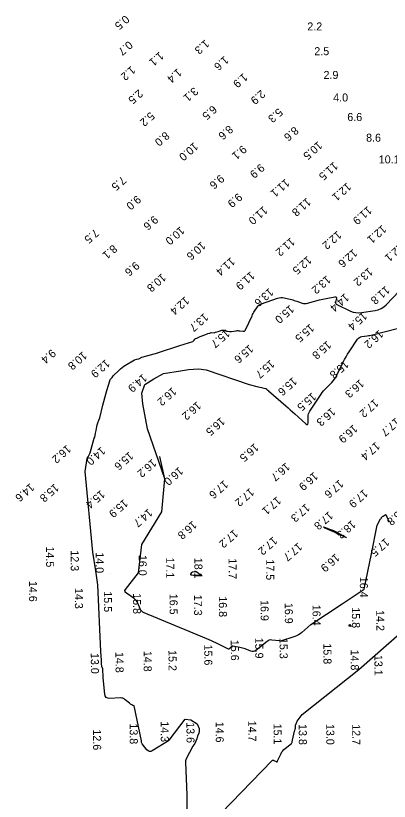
# Model space of a CAD drawing. Extents: x 824616 to 827440, y 158441 to 163197.
# Drawn here: x 824616.2 to 824849.5, y 161147.6 to 161638.3 of the extents above; entities that cross this region are included whole.
import ezdxf

# ---------------------------------------------------------------- set-up
doc = ezdxf.new("R2010")
doc.units = 0
for name, color, linetype in [('V-CHAN-CONT-EL14', 7, 'Continuous'), ('V-CHAN-CONT-EL16', 7, 'Continuous'), ('V-CHAN-CONT-EL18', 7, 'Continuous'), ('V-TOPO-SOUN', 7, 'Continuous')]:
    doc.layers.add(name, color=color, linetype=linetype)

msp = doc.modelspace()

# ---------------------------------------------------------------- linework, layer by layer
at = {"layer": 'V-CHAN-CONT-EL14'}
for points in [[(824704.71, 161427.68), (824718.66, 161432.2), (824726.88, 161434.8), (824727.67, 161435.56), (824728.08, 161436.17), (824728.41, 161436.69), (824729.26, 161436.92), (824731.44, 161438.01), (824734.23, 161438.98), (824736.28, 161439.79), (824737.33, 161440.05), (824738.35, 161440.37), (824740.07, 161440.24), (824740.9, 161440.6), (824741.73, 161440.84), (824742.6, 161440.96), (824743.91, 161441.51), (824744.34, 161441.65), (824744.89, 161441.79), (824745.19, 161441.82), (824745.47, 161441.86), (824745.61, 161441.91), (824745.73, 161441.93), (824745.83, 161441.95), (824745.99, 161441.92), (824746.13, 161441.88), (824746.26, 161441.85), (824746.57, 161441.76), (824746.78, 161441.75), (824746.96, 161441.72), (824747.15, 161441.65), (824747.38, 161441.52), (824747.65, 161441.38), (824747.92, 161441.28), (824748.2, 161441.2), (824748.5, 161441.16), (824749.74, 161441.04), (824750.05, 161441.02), (824750.36, 161441.02), (824750.67, 161441.03), (824750.97, 161441.07), (824753.95, 161441.51), (824754.48, 161441.57), (824755.01, 161441.59), (824755.55, 161441.56), (824756.08, 161441.5), (824758.21, 161441.19), (824758.7, 161441.18), (824759.12, 161441.31), (824759.46, 161441.59), (824759.72, 161442.01), (824763.78, 161450.91), (824764.13, 161451.64), (824764.51, 161452.36), (824764.93, 161453.06), (824765.37, 161453.75), (824767.21, 161456.45), (824767.7, 161457.08), (824768.28, 161457.6), (824768.93, 161458.02), (824769.67, 161458.34), (824779.68, 161461.81), (824780.7, 161462.08), (824781.74, 161462.21), (824782.77, 161462.19), (824783.82, 161462.02), (824788.41, 161460.94), (824789.26, 161460.73), (824790.11, 161460.49), (824790.95, 161460.24), (824791.78, 161459.97), (824795.1, 161458.84), (824795.94, 161458.62), (824796.77, 161458.53), (824797.61, 161458.57), (824798.46, 161458.73), (824805.83, 161460.74), (824806.91, 161461.02), (824807.99, 161461.28), (824809.07, 161461.51), (824810.16, 161461.73), (824815.54, 161462.74), (824816.04, 161462.76), (824816.36, 161462.61), (824816.49, 161462.29), (824816.46, 161461.8), (824815.94, 161459.47), (824815.89, 161458.93), (824816.02, 161458.47), (824816.3, 161458.1), (824816.76, 161457.81), (824825.32, 161453.83), (824826.95, 161453.21), (824828.61, 161452.84), (824830.31, 161452.72), (824832.04, 161452.85), (824840.69, 161454.11), (824842.64, 161454.56), (824844.43, 161455.31), (824846.07, 161456.35), (824847.55, 161457.69), (824855.79, 161466.49)], [(824670.68, 161395.08), (824673.17, 161404.29), (824674.26, 161408.11), (824675.29, 161411), (824676.35, 161412.37), (824677.01, 161413.25), (824680.72, 161416.91), (824681.67, 161417.8), (824682.67, 161418.61), (824683.73, 161419.36), (824684.83, 161420.05), (824690.46, 161423.29), (824691.77, 161423.86), (824693.09, 161424.04), (824694.87, 161425.06), (824698.02, 161425.89), (824704.88, 161427.73)], [(824666.16, 161291.46), (824664.39, 161303.13), (824659.58, 161353.61), (824660.85, 161361.63), (824661.45, 161362.75), (824662.63, 161365.23), (824665.14, 161374.39), (824665.56, 161375.13), (824665.84, 161376.02), (824666.13, 161377.55), (824666.45, 161379.27), (824666.83, 161381.62), (824667.04, 161382.68), (824667.44, 161383.96), (824668.03, 161385.73), (824668.76, 161387.13), (824670.68, 161395.08)], [(824669.31, 161241.2), (824667.57, 161282.73), (824666.16, 161291.46)], [(824675.23, 161289.84), (824675.15, 161289.85)], [(824830.5, 161229.86), (824857.8, 161253.75)], [(824694.69, 161185.29), (824690.25, 161207.15), (824689.43, 161207.43), (824688.66, 161207.79), (824687.93, 161208.24), (824687.25, 161208.77), (824684.61, 161211.05), (824683.92, 161211.54), (824683.18, 161211.89), (824682.39, 161212.08), (824681.54, 161212.12), (824674.89, 161211.88), (824673.65, 161212.01), (824672.72, 161212.5), (824672.11, 161213.35), (824671.81, 161214.56), (824670.78, 161224.72), (824670.86, 161226.63), (824670.67, 161228.58), (824670.63, 161229.39), (824670.52, 161230.38), (824670.09, 161231.7), (824669.76, 161233.44), (824669.76, 161234.34), (824669.87, 161235.76), (824669.56, 161238.37), (824669.31, 161241.2)], [(824738.15, 161133.53), (824776.31, 161172.97), (824776.58, 161173.19), (824776.87, 161173.29), (824777.17, 161173.28), (824777.49, 161173.15), (824778.81, 161172.43), (824779.11, 161172.31), (824779.38, 161172.32), (824779.6, 161172.47), (824779.78, 161172.75), (824781.97, 161177.51), (824782.43, 161178.39), (824782.98, 161179.19), (824783.63, 161179.91), (824784.37, 161180.57), (824788.39, 161183.74), (824788.73, 161184.07), (824788.8, 161184.34), (824788.84, 161184.76), (824788.95, 161185.68), (824790.39, 161191.42), (824790.44, 161191.73), (824790.72, 161192.62), (824790.77, 161192.74), (824790.83, 161193.04), (824790.94, 161195.37), (824791.15, 161195.64), (824791.42, 161195.91), (824792.02, 161197.67), (824795.17, 161201.73), (824830.5, 161229.86)], [(824712, 161185.81), (824722.02, 161198.8), (824725.52, 161198.49), (824729.62, 161196.02), (824730.85, 161193.09), (824730.75, 161191.43), (824730.49, 161189.99), (824729.78, 161188.36), (824729.21, 161186.58), (824728.77, 161185.12), (824727.97, 161183.58), (824726.89, 161181.96), (824722.63, 161174.09), (824722.16, 161172.86), (824722.28, 161171.93), (824723.06, 161151.41), (824723.12, 161150.99)], [(824711.96, 161185.72), (824711.9, 161185.59), (824711.63, 161185.37), (824701.52, 161179.11), (824700.56, 161178.68), (824699.67, 161178.64), (824698.85, 161178.99), (824698.1, 161179.73), (824695.24, 161183.44), (824694.76, 161184.28), (824694.75, 161184.93), (824694.69, 161185.29)], [(824723.12, 161150.99), (824723.05, 161142.63)]]:
    msp.add_lwpolyline(points, dxfattribs=at)
msp.add_lwpolyline([(824824.44, 161257.3), (824824.68, 161257.91), (824824.72, 161257.99), (824824.76, 161258.02), (824824.82, 161258), (824824.88, 161257.93), (824825.65, 161256.79), (824825.69, 161256.73), (824825.68, 161256.69), (824825.65, 161256.68), (824825.58, 161256.68), (824824.39, 161256.92), (824824.35, 161256.94), (824824.33, 161256.96), (824824.33, 161256.99), (824824.33, 161257.03)], close=True, dxfattribs=at)
at = {"layer": 'V-CHAN-CONT-EL16'}
for points in [[(824709.41, 161349.04), (824698.46, 161380.23), (824695.49, 161395.93), (824694.93, 161402.6), (824696.85, 161407.97), (824702.55, 161411.39), (824708.44, 161414.77), (824719.18, 161416.54), (824724.17, 161417.37), (824730.38, 161417.69), (824735.21, 161417.09), (824762, 161408.03), (824766.73, 161406.78), (824769.78, 161405.99), (824771.07, 161405.72), (824772.15, 161405.54), (824772.42, 161405.37), (824772.61, 161405.23), (824772.72, 161405.19), (824772.82, 161405.11), (824773.31, 161404.57), (824773.36, 161404.51), (824773.42, 161404.46), (824773.48, 161404.42), (824773.55, 161404.38), (824773.82, 161404.24), (824773.88, 161404.2), (824773.95, 161404.16), (824774.01, 161404.12), (824774.07, 161404.07), (824784.89, 161394.52), (824786.28, 161393.29), (824787.67, 161392.06), (824789.06, 161390.81), (824790.44, 161389.57), (824797.3, 161383.37), (824797.92, 161382.93), (824798.37, 161382.89), (824798.64, 161383.25), (824798.74, 161384), (824798.78, 161387.82), (824798.85, 161388.76), (824799.06, 161389.65), (824799.39, 161390.51), (824799.86, 161391.32), (824806.89, 161401.89), (824807.61, 161402.91), (824808.38, 161403.9), (824809.19, 161404.84), (824810.06, 161405.74), (824813.62, 161409.28), (824814.47, 161410.19), (824815.23, 161411.17), (824815.91, 161412.2), (824816.5, 161413.3), (824820.76, 161421.99), (824821.6, 161423.64), (824822.49, 161425.25), (824823.45, 161426.84), (824824.45, 161428.39), (824829.72, 161436.22), (824830.23, 161436.84), (824830.84, 161437.32), (824831.53, 161437.65), (824832.31, 161437.85), (824835.63, 161438.33), (824836.46, 161438.46), (824837.28, 161438.62), (824838.1, 161438.79), (824838.91, 161438.98), (824854.39, 161442.87)], [(824684.79, 161279.79), (824692.79, 161290.29), (824695.05, 161308.06), (824707.49, 161328.3), (824709.41, 161349.04), (824706.29, 161362.98)], [(824849.57, 161322.34), (824849.26, 161322.71), (824848.98, 161323.11), (824848.74, 161323.53), (824848.53, 161323.97), (824847.67, 161326.04), (824847.52, 161326.3), (824847.32, 161326.43), (824847.08, 161326.44), (824846.81, 161326.31), (824845.62, 161325.55), (824845.31, 161325.39), (824844.89, 161325.15), (824844.67, 161324.88), (824844.44, 161324.58), (824843.99, 161323.96)], [(824800.46, 161257.92), (824820.08, 161271.01), (824833.72, 161280.11), (824838.27, 161302.2), (824841.94, 161320.04), (824843.99, 161323.96)], [(824800.46, 161257.92), (824794.89, 161252.97), (824793.87, 161252.16), (824792.78, 161251.46), (824791.63, 161250.88), (824790.4, 161250.43), (824781.54, 161247.62), (824781.49, 161247.61), (824781.44, 161247.61), (824781.4, 161247.61), (824781.35, 161247.63), (824781.16, 161247.7), (824781.12, 161247.72), (824781.07, 161247.73), (824781.02, 161247.74), (824780.97, 161247.75), (824776.12, 161248.31), (824775.31, 161248.33), (824774.56, 161248.19), (824773.84, 161247.9), (824773.17, 161247.46), (824766.22, 161241.82), (824765.47, 161241.35), (824764.7, 161241.11), (824763.88, 161241.11), (824763.03, 161241.33), (824759.42, 161242.76), (824758.62, 161243.05), (824757.81, 161243.3), (824756.99, 161243.51), (824756.15, 161243.68), (824751.79, 161244.45), (824751.47, 161244.47), (824751.17, 161244.41), (824750.91, 161244.27), (824750.67, 161244.05), (824749.78, 161243.01), (824749.55, 161242.8), (824749.3, 161242.69), (824749.02, 161242.69), (824748.72, 161242.79), (824741.14, 161246.53), (824739.77, 161247.19), (824738.39, 161247.83), (824737, 161248.44), (824735.6, 161249.04), (824696.42, 161265.26), (824695.6, 161265.69), (824694.9, 161266.26), (824694.34, 161266.95), (824693.9, 161267.78), (824692.42, 161271.34), (824692, 161272.19), (824691.47, 161272.96), (824690.84, 161273.64), (824690.11, 161274.25), (824685.41, 161277.62), (824684.65, 161278.25), (824684.47, 161278.62), (824684.33, 161279.22), (824684.79, 161279.79)]]:
    msp.add_lwpolyline(points, dxfattribs=at)
at = {"layer": 'V-CHAN-CONT-EL18'}
for points in [[(824815.42, 161315.68), (824816.41, 161315.22), (824817.39, 161314.75), (824821.72, 161312.68), (824822.51, 161312.31), (824822.79, 161312.21), (824822.54, 161312.37), (824821.78, 161312.79), (824816.51, 161315.65), (824815.65, 161316.09), (824814.77, 161316.51), (824813.87, 161316.89), (824812.96, 161317.23), (824809.28, 161318.54), (824808.59, 161318.77), (824808.35, 161318.83), (824808.56, 161318.71), (824809.23, 161318.41), (824813.43, 161316.57), (824814.43, 161316.13)], [(824727.76, 161288.63), (824727.47, 161288.65), (824727.17, 161288.67), (824725.93, 161288.81), (824725.7, 161288.87), (824725.57, 161288.98), (824725.55, 161289.15), (824725.62, 161289.38), (824726.1, 161290.39), (824726.24, 161290.62), (824726.42, 161290.79), (824726.64, 161290.91), (824726.89, 161290.97), (824728.22, 161291.14), (824728.53, 161291.15), (824728.82, 161291.1), (824729.09, 161290.99), (824729.35, 161290.83), (824731.44, 161289.27), (824731.75, 161288.98), (824731.81, 161288.78), (824731.64, 161288.66), (824731.22, 161288.62), (824728.36, 161288.61), (824728.06, 161288.62)]]:
    msp.add_lwpolyline(points, close=True, dxfattribs=at)

# ---------------------------------------------------------------- texts
at = {"layer": 'V-TOPO-SOUN'}
for s, rotation, p in [('0.5', 221.3, (824684.53, 161638.96)), ('0.7', 221.3, (824686.58, 161622.91)), ('1.3', 221.3, (824734.47, 161623.64)), ('1.1', 221.3, (824706.01, 161616.15)), ('1.6', 221.3, (824746.55, 161613.46)), ('1.2', 221.3, (824688.32, 161607.21)), ('1.4', 221.3, (824717.27, 161605.68)), ('1.9', 221.3, (824758.4, 161602.7)), ('2.5', 221.3, (824692.98, 161592.54)), ('3.1', 221.3, (824727.49, 161593.98)), ('2.9', 221.3, (824769.38, 161592.28)), ('6.5', 221.3, (824739.17, 161582.66)), ('5.2', 221.3, (824700.27, 161578.56)), ('5.3', 221.3, (824780.29, 161580.9)), ('8.6', 221.3, (824749.27, 161570.21)), ('8.6', 221.3, (824790.19, 161569.41)), ('8.0', 221.3, (824709.55, 161566.23)), ('10.0 ', 221.3, (824727.48, 161559.53)), ('9.1', 221.3, (824757.74, 161557.73)), ('10.5 ', 221.3, (824805.03, 161560.16)), ('11.5 ', 221.3, (824814.8, 161547.33)), ('9.9', 221.3, (824768.89, 161546.18)), ('7.5', 221.3, (824682.52, 161538.4)), ('9.6', 221.3, (824743.79, 161539.42)), ('11.1 ', 221.3, (824784.61, 161536.74)), ('12.1 ', 221.3, (824823.08, 161534.35)), ('9.9', 221.3, (824755.02, 161527.85)), ('9.0', 221.3, (824691.76, 161526.37)), ('11.8 ', 221.3, (824797.92, 161524.83)), ('11.0 ', 221.3, (824770.87, 161519.63)), ('11.9 ', 221.3, (824835.98, 161519.61)), ('9.6', 221.3, (824702.47, 161513.74)), ('12.1 ', 221.3, (824845.02, 161507.85)), ('7.5', 221.3, (824665.56, 161505.48)), ('10.0 ', 221.3, (824719.01, 161506.98)), ('12.2 ', 221.3, (824817.01, 161504.2)), ('11.2 ', 221.3, (824787.89, 161499.99)), ('8.1', 221.3, (824676.91, 161495.6)), ('10.6 ', 221.3, (824732.2, 161497.51)), ('12.6 ', 221.3, (824826.9, 161492.89)), ('12.1 ', 221.3, (824855.98, 161496.39)), ('12.5 ', 221.3, (824798.38, 161488.5)), ('9.6', 221.3, (824690.83, 161485.06)), ('11.4 ', 221.3, (824750.54, 161487.66)), ('11.9 ', 221.3, (824762.87, 161478.84)), ('13.2 ', 221.3, (824836.55, 161481.26)), ('10.8 ', 221.3, (824707.4, 161477.57)), ('13.2 ', 221.3, (824810.34, 161476.34)), ('13.6 ', 221.3, (824774.53, 161468.48)), ('11.8 ', 221.3, (824847.17, 161469.82)), ('14.4 ', 221.3, (824821.74, 161465.15)), ('12.4 ', 221.3, (824721.96, 161463.21)), ('15.0 ', 221.3, (824787.41, 161457.92)), ('15.4 ', 221.3, (824833, 161453.58)), ('13.7 ', 221.3, (824733.89, 161452.82)), ('15.5 ', 221.3, (824799.97, 161446.14)), ('15.7 ', 221.3, (824747.36, 161442.72)), ('16.2 ', 221.3, (824843.15, 161442.36)), ('15.8 ', 221.3, (824810.61, 161435.53)), ('9.4', 221.3, (824638.62, 161430.34)), ('15.6 ', 221.3, (824761.97, 161433.07)), ('10.8 ', 221.3, (824658.07, 161428.88)), ('12.9 ', 221.3, (824672.38, 161423.97)), ('15.7 ', 221.3, (824775.22, 161423.61)), ('15.8 ', 221.3, (824821.55, 161423.39)), ('14.9 ', 221.3, (824695.58, 161414.89)), ('15.6 ', 221.3, (824789.25, 161412.79)), ('16.3 ', 221.3, (824831.12, 161411.43)), ('16.2 ', 221.3, (824714, 161406.5)), ('15.5 ', 221.3, (824801.23, 161403.19)), ('16.2 ', 221.3, (824729.37, 161397.59)), ('17.2 ', 221.3, (824840.15, 161399.16)), ('16.3 ', 221.3, (824813.32, 161393.76)), ('16.5 ', 221.3, (824744.26, 161387.77)), ('17.7 ', 221.3, (824853.48, 161387.47)), ('16.9 ', 221.3, (824827.07, 161383.21)), ('16.2 ', 221.3, (824648.14, 161370.55)), ('16.5 ', 221.3, (824765.32, 161371.5)), ('17.4 ', 221.3, (824841.05, 161372.39)), ('14.0 ', 221.3, (824669.61, 161369.32)), ('15.6 ', 221.3, (824687.09, 161366.25)), ('16.2 ', 221.3, (824701.48, 161361.73)), ('16.0 ', 221.3, (824718.17, 161356.73)), ('16.7 ', 221.3, (824784.86, 161359.44)), ('16.9 ', 221.3, (824802.33, 161353.54)), ('14.6 ', 221.3, (824625.23, 161346.53)), ('15.8 ', 221.3, (824640.52, 161346.32)), ('17.6 ', 221.3, (824746.25, 161348.42)), ('17.6 ', 221.3, (824818.24, 161348.78)), ('15.4 ', 221.3, (824669.29, 161342.26)), ('17.2 ', 221.3, (824762.47, 161343.56)), ('17.9 ', 221.3, (824833.48, 161342.77)), ('15.9 ', 221.3, (824683.7, 161336.59)), ('17.1 ', 221.3, (824779.31, 161338.28)), ('17.3 ', 221.3, (824797.29, 161333.82)), ('15.8 ', 221.3, (824857.27, 161331.68)), ('14.7 ', 221.3, (824699.05, 161330.71)), ('17.8 ', 221.3, (824811.76, 161328.97)), ('16.8 ', 221.3, (824726.67, 161323.07)), ('18.3 ', 221.3, (824825.92, 161323.42)), ('17.2 ', 221.3, (824752.46, 161317.68)), ('17.2 ', 221.3, (824776.95, 161313.21)), ('17.5 ', 221.3, (824846.96, 161312.28)), ('14.5 ', 270, (824635.2, 161306.75)), ('17.7 ', 221.3, (824792.51, 161309.45)), ('12.3 ', 270, (824650.61, 161304.34)), ('14.0 ', 270, (824666.16, 161303.12)), ('16.9 ', 221.3, (824815.9, 161302.62)), ('16.0 ', 270, (824693.01, 161301.5)), ('17.1 ', 270, (824710.17, 161299.85)), ('18.1 ', 270, (824727.82, 161299.68)), ('17.7 ', 270, (824749.15, 161299.38)), ('17.5 ', 270, (824772.62, 161298.7)), ('16.4 ', 270, (824831.1, 161287.82)), ('14.6 ', 270.3, (824624.49, 161285.24)), ('14.3 ', 270.3, (824653.13, 161280.82)), ('15.5 ', 270.3, (824671.28, 161278.73)), ('15.8 ', 270.3, (824689.43, 161277.56)), ('16.5 ', 270.3, (824712.3, 161277.19)), ('17.3 ', 270.3, (824727.54, 161276.57)), ('16.8 ', 270.3, (824743.05, 161275.64)), ('16.9 ', 270.3, (824769.12, 161273.26)), ('16.9 ', 270.3, (824784.22, 161271.51)), ('16.4 ', 270.3, (824801.54, 161270.33)), ('15.8 ', 270.3, (824826.12, 161268.74)), ('14.2 ', 270.3, (824841.35, 161266.97)), ('15.6 ', 270.3, (824750.52, 161248.43)), ('15.9 ', 270.3, (824765.75, 161249.76)), ('15.3 ', 270.3, (824780.96, 161249.62)), ('15.6 ', 270.3, (824733.95, 161245.48)), ('15.8 ', 270.3, (824808.34, 161246.19)), ('13.0 ', 270.3, (824663.11, 161240.21)), ('14.8 ', 270.3, (824678.5, 161240.88)), ('14.8 ', 270.3, (824696.09, 161241.53)), ('15.2 ', 270.3, (824711.61, 161242)), ('14.8 ', 270.3, (824825.41, 161242.34)), ('13.1 ', 270.3, (824840.2, 161239.03)), ('13.8 ', 270.3, (824687.38, 161196.22)), ('14.3 ', 270.3, (824706.75, 161197.56)), ('13.6 ', 270.3, (824722.82, 161196.97)), ('14.6 ', 270.3, (824741.07, 161197.28)), ('14.7 ', 270.3, (824761.38, 161197.9)), ('15.1 ', 270.3, (824777.22, 161196.11)), ('13.8 ', 270.3, (824792.96, 161195.79)), ('13.0 ', 270.3, (824810.12, 161195.87)), ('12.7 ', 270.3, (824826.32, 161195.71)), ('12.6 ', 270.3, (824664.5, 161192.47))]:
    msp.add_text(s, height=5, rotation=rotation, dxfattribs=at).set_placement(p)
for s, p in [('2.2', (824798.29, 161629.11)), ('2.5', (824802.67, 161613.65)), ('2.9', (824808.42, 161598.81)), ('4.0', (824814.46, 161584.74)), ('6.6', (824823.25, 161572.53)), ('8.6', (824834.99, 161559.6)), ('10.1 ', (824842.91, 161546.06))]:
    msp.add_text(s, height=5, dxfattribs=at).set_placement(p)

doc.saveas('drawing.dxf')
